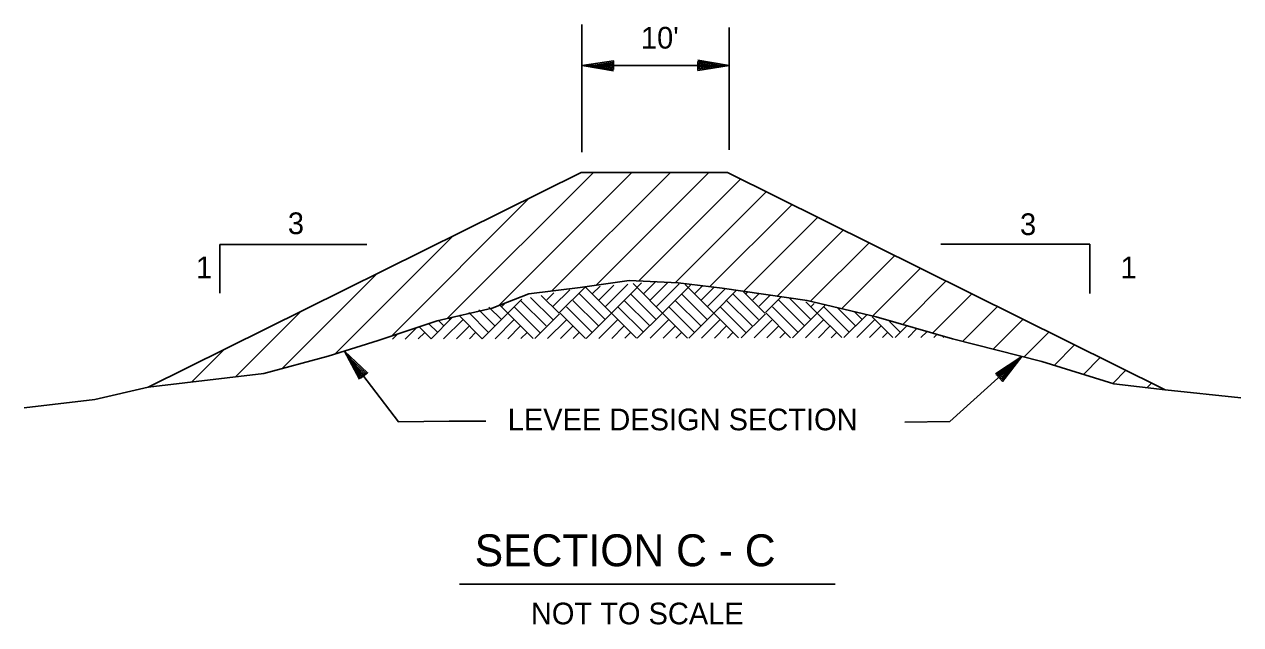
# Model space of a CAD drawing. Extents: x 2127959 to 2137375, y 2146193 to 2153470.
# Drawn here: x 2131652 to 2133498, y 2148312 to 2149223 of the extents above; entities that cross this region are included whole.
import ezdxf

# ---------------------------------------------------------------- set-up
doc = ezdxf.new("R2010")
doc.units = 0
for name, color, linetype in [('Level 1', 7, 'Continuous'), ('Level 3', 7, 'Continuous'), ('Level 5', 7, 'Continuous'), ('Level 50', 7, 'Continuous'), ('Level 63', 7, 'Continuous')]:
    doc.layers.add(name, color=color, linetype=linetype)

msp = doc.modelspace()

# ---------------------------------------------------------------- linework, layer by layer
at = {"layer": 'Level 1'}
for p, q in [((2132496.987, 2148998.226), (2131839.745, 2148672.512)), ((2132496.987, 2148998.226), (2131839.745, 2148672.512)), ((2132496.987, 2148998.226), (2131839.745, 2148672.512)), ((2132496.987, 2148998.226), (2132719.089, 2148998.226)), ((2132496.987, 2148998.226), (2132719.089, 2148998.226)), ((2132496.987, 2148998.226), (2132719.089, 2148998.226)), ((2132719.089, 2148998.226), (2133383.437, 2148668.257)), ((2132719.089, 2148998.226), (2133383.437, 2148668.257)), ((2132719.089, 2148998.226), (2133383.437, 2148668.257))]:
    msp.add_line(p, q, dxfattribs=at)
at = {"layer": 'Level 3'}
for p, q in [((2132497.781, 2149028.681), (2132497.781, 2149222.769)), ((2132721.264, 2149032.313), (2132721.264, 2149218.04)), ((2132497.781, 2149160.417), (2132609.509, 2149160.417)), ((2132721.264, 2149160.417), (2132609.509, 2149160.417)), ((2132171.512, 2148888.717), (2131948.22, 2148888.717)), ((2132171.512, 2148888.717), (2131948.22, 2148888.717)), ((2132171.512, 2148888.717), (2131948.22, 2148888.717)), ((2131948.22, 2148888.717), (2131948.22, 2148814.697)), ((2133042.777, 2148889.177), (2133268.647, 2148889.177)), ((2133042.777, 2148889.177), (2133268.647, 2148889.177)), ((2133042.777, 2148889.177), (2133268.647, 2148889.177)), ((2133268.647, 2148889.177), (2133268.647, 2148814.544)), ((2133268.647, 2148889.177), (2133268.647, 2148814.544)), ((2133268.647, 2148889.177), (2133268.647, 2148814.544))]:
    msp.add_line(p, q, dxfattribs=at)
for points in [[(2132137.319, 2148727.148), (2132219.454, 2148619.815), (2132296.18, 2148620.596), (2132352.068, 2148620.596)], [(2133165.513, 2148718.847), (2133056.395, 2148620.44), (2132987.946, 2148619.334)]]:
    msp.add_lwpolyline(points, dxfattribs=at)
at = {"layer": 'Level 5'}
for p, q in [((2132294.09, 2148776.813), (2132515.512, 2148998.226)), ((2132371.523, 2148795.886), (2132573.867, 2148998.226)), ((2132451.988, 2148818.019), (2132632.193, 2148998.226)), ((2132519.14, 2148826.799), (2132690.547, 2148998.226)), ((2132584.14, 2148833.467), (2132738.996, 2148988.325)), ((2132639.983, 2148830.979), (2132777.99, 2148968.962)), ((2132209.156, 2148750.201), (2132418.059, 2148959.107)), ((2132692.246, 2148824.887), (2132816.977, 2148949.598)), ((2132743.577, 2148817.864), (2132855.946, 2148930.234)), ((2132794.535, 2148810.497), (2132894.937, 2148910.874)), ((2132123.323, 2148722.735), (2132302.388, 2148901.789)), ((2132845.08, 2148802.683), (2132933.93, 2148891.531)), ((2132892.234, 2148791.485), (2132972.896, 2148872.17)), ((2132042.795, 2148700.549), (2132186.715, 2148844.471)), ((2132939.387, 2148780.304), (2133011.888, 2148852.805)), ((2132417.489, 2148813.748), (2132495.4, 2148823.365)), ((2132417.489, 2148813.748), (2132495.4, 2148823.365)), ((2132417.489, 2148813.748), (2132495.4, 2148823.365)), ((2132479.338, 2148820.108), (2132454.345, 2148795.093)), ((2132464.067, 2148785.363), (2132502.728, 2148824.028)), ((2132495.4, 2148823.365), (2132569.575, 2148834.103)), ((2132495.4, 2148823.365), (2132569.575, 2148834.103)), ((2132495.4, 2148823.365), (2132569.575, 2148834.103)), ((2132503.737, 2148823.501), (2132542.642, 2148784.596)), ((2132513.51, 2148813.792), (2132525.418, 2148825.719)), ((2132546.468, 2148827.283), (2132523.257, 2148804.046)), ((2132567.463, 2148828.825), (2132532.961, 2148794.321)), ((2132542.707, 2148784.596), (2132581.589, 2148823.501)), ((2132569.575, 2148834.103), (2132643.946, 2148830.8)), ((2132569.575, 2148834.103), (2132643.946, 2148830.8)), ((2132569.575, 2148834.103), (2132643.946, 2148830.8)), ((2132581.589, 2148823.501), (2132575.648, 2148829.439)), ((2132575.648, 2148829.439), (2132581.589, 2148823.501)), ((2132588.501, 2148830.384), (2132581.431, 2148823.322)), ((2132581.589, 2148823.501), (2132620.49, 2148784.596)), ((2132591.335, 2148813.748), (2132609.509, 2148831.947)), ((2132601.036, 2148804.046), (2132627.711, 2148830.69)), ((2132645.421, 2148828.911), (2132610.787, 2148794.302)), ((2132620.315, 2148784.751), (2132659.065, 2148823.475)), ((2132643.946, 2148830.8), (2132711.011, 2148822.593)), ((2132643.946, 2148830.8), (2132711.011, 2148822.593)), ((2132643.946, 2148830.8), (2132711.011, 2148822.593)), ((2132654.554, 2148828.008), (2132659.236, 2148823.322)), ((2132659.065, 2148823.475), (2132662.757, 2148827.198)), ((2132697.963, 2148784.596), (2132659.065, 2148823.475)), ((2132668.766, 2148813.775), (2132680.407, 2148825.434)), ((2132698.119, 2148823.65), (2132678.514, 2148804.026)), ((2132715.811, 2148821.894), (2132688.216, 2148794.321)), ((2132697.963, 2148784.596), (2132732.794, 2148819.428)), ((2132711.011, 2148822.593), (2132839.621, 2148803.961)), ((2132775.813, 2148784.596), (2132742.343, 2148818.041)), ((2132984.868, 2148767.441), (2133050.873, 2148833.444)), ((2132361.467, 2148791.966), (2132417.489, 2148813.748)), ((2132361.467, 2148791.966), (2132417.489, 2148813.748)), ((2132361.467, 2148791.966), (2132417.489, 2148813.748)), ((2132381.886, 2148800.48), (2132375.701, 2148794.302)), ((2132385.427, 2148784.572), (2132406.572, 2148805.716)), ((2132404.944, 2148804.026), (2132443.849, 2148765.126)), ((2132420.019, 2148808.383), (2132453.551, 2148774.841)), ((2132463.275, 2148784.572), (2132436.28, 2148811.596)), ((2132455.115, 2148815.318), (2132444.614, 2148804.815)), ((2132523.193, 2148765.149), (2132484.293, 2148804.046)), ((2132494.035, 2148813.792), (2132532.961, 2148774.868)), ((2132600.886, 2148765.316), (2132562.137, 2148804.046)), ((2132571.881, 2148813.792), (2132610.634, 2148775.058)), ((2132639.613, 2148804.026), (2132678.514, 2148765.143)), ((2132649.293, 2148813.775), (2132688.216, 2148774.857)), ((2132717.455, 2148804.026), (2132756.361, 2148765.143)), ((2132727.162, 2148813.775), (2132766.087, 2148774.857)), ((2132747.411, 2148814.567), (2132749.802, 2148816.987)), ((2132766.836, 2148814.5), (2132757.152, 2148804.815)), ((2132783.796, 2148812.056), (2132766.854, 2148795.116)), ((2132776.58, 2148785.389), (2132800.546, 2148809.352)), ((2132835.705, 2148765.16), (2132796.827, 2148804.07)), ((2132813.639, 2148806.732), (2132845.494, 2148774.881)), ((2132837.839, 2148801.91), (2132855.155, 2148784.616)), ((2132839.621, 2148803.961), (2132944.753, 2148779.033)), ((2132839.621, 2148803.961), (2132944.753, 2148779.033)), ((2132839.621, 2148803.961), (2132944.753, 2148779.033)), ((2132850.534, 2148799.38), (2132845.494, 2148794.344)), ((2133030.15, 2148754.363), (2133089.841, 2148814.082)), ((2131971.897, 2148687.996), (2132071.068, 2148787.149)), ((2132278.028, 2148773.192), (2132361.467, 2148791.966)), ((2132278.028, 2148773.192), (2132361.467, 2148791.966)), ((2132278.028, 2148773.192), (2132361.467, 2148791.966)), ((2132346.68, 2148745.847), (2132311.034, 2148781.515)), ((2132356.231, 2148755.375), (2132326.088, 2148785.542)), ((2132341.448, 2148789.656), (2132365.979, 2148765.126)), ((2132385.427, 2148784.572), (2132346.594, 2148745.746)), ((2132356.758, 2148793.775), (2132375.701, 2148774.841)), ((2132385.427, 2148784.572), (2132372.115, 2148797.885)), ((2132424.091, 2148745.985), (2132385.496, 2148784.572)), ((2132434.098, 2148755.375), (2132395.152, 2148794.302)), ((2132464.067, 2148783.805), (2132426.24, 2148745.992)), ((2132464.838, 2148784.596), (2132503.212, 2148746.229)), ((2132513.51, 2148755.407), (2132474.568, 2148794.321)), ((2132542.707, 2148784.596), (2132504.335, 2148746.23)), ((2132542.707, 2148784.596), (2132580.819, 2148746.466)), ((2132591.161, 2148755.596), (2132552.433, 2148794.321)), ((2132582.027, 2148746.473), (2132620.315, 2148784.751)), ((2132658.356, 2148746.711), (2132620.315, 2148784.751)), ((2132668.766, 2148755.39), (2132629.842, 2148794.321)), ((2132697.963, 2148784.596), (2132660.097, 2148746.713)), ((2132735.657, 2148746.942), (2132698.03, 2148784.596)), ((2132746.614, 2148755.39), (2132707.687, 2148794.321)), ((2132776.58, 2148783.826), (2132739.727, 2148746.952)), ((2132777.374, 2148784.616), (2132814.779, 2148747.187)), ((2132826.022, 2148755.414), (2132787.102, 2148794.344)), ((2132855.22, 2148784.616), (2132817.82, 2148747.199)), ((2132855.22, 2148784.616), (2132866.777, 2148796.148)), ((2132855.22, 2148784.616), (2132892.409, 2148747.43)), ((2132903.698, 2148755.614), (2132864.948, 2148794.344)), ((2132913.402, 2148765.322), (2132886.512, 2148792.231)), ((2132895.514, 2148747.436), (2132929.682, 2148781.602)), ((2132911.662, 2148786.554), (2132923.146, 2148775.076)), ((2133075.809, 2148741.689), (2133128.834, 2148794.719)), ((2132188.674, 2148743.367), (2132278.028, 2148773.192)), ((2132188.674, 2148743.367), (2132278.028, 2148773.192)), ((2132188.674, 2148743.367), (2132278.028, 2148773.192)), ((2132229.865, 2148745.385), (2132247.116, 2148762.64)), ((2132250.942, 2148763.82), (2132269.074, 2148745.692)), ((2132278.648, 2148755.582), (2132265.796, 2148768.407)), ((2132268.9, 2148745.847), (2132302.212, 2148779.152)), ((2132288.35, 2148765.306), (2132280.667, 2148772.999)), ((2132288.02, 2148745.566), (2132317.526, 2148775.076)), ((2132295.743, 2148777.419), (2132298.098, 2148775.05)), ((2132327.255, 2148765.29), (2132307.559, 2148745.623)), ((2132366.131, 2148745.807), (2132395.152, 2148774.841)), ((2132385.602, 2148745.861), (2132404.881, 2148765.126)), ((2132445.759, 2148746.056), (2132473.794, 2148774.077)), ((2132465.259, 2148746.112), (2132483.52, 2148764.361)), ((2132523.852, 2148746.288), (2132552.433, 2148774.868)), ((2132543.347, 2148746.351), (2132562.137, 2148765.149)), ((2132601.505, 2148746.532), (2132630.06, 2148775.089)), ((2132639.761, 2148765.312), (2132621.063, 2148746.592)), ((2132679.615, 2148746.773), (2132707.687, 2148774.857)), ((2132699.108, 2148746.835), (2132717.413, 2148765.143)), ((2132759.265, 2148747.02), (2132786.331, 2148774.09)), ((2132778.737, 2148747.075), (2132796.034, 2148764.373)), ((2132837.354, 2148747.258), (2132864.948, 2148774.881)), ((2132856.826, 2148747.32), (2132874.673, 2148765.16)), ((2132914.985, 2148747.497), (2132942.576, 2148775.099)), ((2132952.298, 2148765.319), (2132934.547, 2148747.556)), ((2132969.947, 2148747.669), (2132938.397, 2148779.216)), ((2132944.753, 2148779.033), (2133060.534, 2148745.58)), ((2132944.753, 2148779.033), (2133060.534, 2148745.58)), ((2132944.753, 2148779.033), (2133060.534, 2148745.58)), ((2132981.299, 2148755.407), (2132964.695, 2148772.004)), ((2132990.74, 2148764.854), (2132973.558, 2148747.68)), ((2133122.323, 2148729.845), (2133167.825, 2148775.351)), ((2132210.367, 2148745.325), (2132219.016, 2148753.963)), ((2132259.37, 2148755.39), (2132249.404, 2148745.446)), ((2132336.999, 2148755.614), (2132327.073, 2148745.686)), ((2132414.624, 2148755.375), (2132405.162, 2148745.927)), ((2132493.271, 2148754.613), (2132484.815, 2148746.171)), ((2132571.881, 2148755.407), (2132562.907, 2148746.41)), ((2132649.512, 2148755.622), (2132640.535, 2148746.651)), ((2132727.162, 2148755.39), (2132718.668, 2148746.896)), ((2132805.781, 2148754.627), (2132798.301, 2148747.138)), ((2132884.422, 2148755.414), (2132876.389, 2148747.382)), ((2132962.045, 2148755.632), (2132954.019, 2148747.619)), ((2132993.096, 2148747.736), (2133006.008, 2148760.657)), ((2133012.595, 2148747.803), (2133021.258, 2148756.48)), ((2133036.552, 2148752.278), (2133032.151, 2148747.86)), ((2133047.224, 2148747.904), (2133045.245, 2148749.897)), ((2133060.534, 2148745.58), (2133196.254, 2148711.019)), ((2133060.534, 2148745.58), (2133196.254, 2148711.019)), ((2133060.534, 2148745.58), (2133196.254, 2148711.019)), ((2133168.818, 2148718.007), (2133206.815, 2148755.987)), ((2131905.825, 2148680.256), (2131955.395, 2148729.835)), ((2132112.741, 2148719.384), (2132188.674, 2148743.367)), ((2132112.741, 2148719.384), (2132188.674, 2148743.367)), ((2132112.741, 2148719.384), (2132188.674, 2148743.367)), ((2133214.54, 2148705.368), (2133245.78, 2148736.626)), ((2132014.892, 2148693.034), (2132112.741, 2148719.384)), ((2132014.892, 2148693.034), (2132112.741, 2148719.384)), ((2132014.892, 2148693.034), (2132112.741, 2148719.384)), ((2133196.254, 2148711.019), (2133305.519, 2148677.253)), ((2133196.254, 2148711.019), (2133305.519, 2148677.253)), ((2133196.254, 2148711.019), (2133305.519, 2148677.253)), ((2133259.094, 2148691.597), (2133284.771, 2148717.264)), ((2131839.745, 2148672.512), (2132014.892, 2148693.034)), ((2131839.745, 2148672.512), (2132014.892, 2148693.034)), ((2131839.745, 2148672.512), (2132014.892, 2148693.034)), ((2133303.671, 2148677.821), (2133323.763, 2148697.905)), ((2131758.664, 2148653.735), (2131839.745, 2148672.512)), ((2131758.664, 2148653.735), (2131839.745, 2148672.512)), ((2131758.664, 2148653.735), (2131839.745, 2148672.512)), ((2133305.519, 2148677.253), (2133383.437, 2148668.257)), ((2133305.519, 2148677.253), (2133383.437, 2148668.257)), ((2133305.519, 2148677.253), (2133383.437, 2148668.257)), ((2133355.665, 2148671.463), (2133362.733, 2148678.54)), ((2131651.552, 2148641.115), (2131758.664, 2148653.735)), ((2131651.552, 2148641.115), (2131758.664, 2148653.735)), ((2131651.552, 2148641.115), (2131758.664, 2148653.735)), ((2133383.437, 2148668.257), (2133497.853, 2148656.264)), ((2133383.437, 2148668.257), (2133497.853, 2148656.264)), ((2133383.437, 2148668.257), (2133497.853, 2148656.264))]:
    msp.add_line(p, q, dxfattribs=at)
at = {"layer": 'Level 50'}
for p, q in [((2132498.491, 2149160.146), (2132498.491, 2149160.146)), ((2132511.614, 2149160.042), (2132511.614, 2149160.042)), ((2132708.125, 2149160.475), (2132708.125, 2149160.475)), ((2132721.25, 2149160.37), (2132721.25, 2149160.37)), ((2132137.524, 2148726.851), (2132137.524, 2148726.851)), ((2132145.515, 2148716.455), (2132145.515, 2148716.455)), ((2133155.879, 2148709.905), (2133155.879, 2148709.905)), ((2133165.544, 2148718.786), (2133165.544, 2148718.786))]:
    msp.add_line(p, q, dxfattribs=at)
for points in [[(2132674.109, 2149168.535), (2132721.25, 2149160.37), (2132674.013, 2149152.882), (2132674.106, 2149166.254), (2132708.125, 2149160.475), (2132676.059, 2149155.396), (2132676.101, 2149163.987), (2132695.51, 2149160.565), (2132678.088, 2149157.903), (2132678.11, 2149161.429), (2132682.384, 2149160.652)], [(2132545.63, 2149151.986), (2132498.491, 2149160.146), (2132545.725, 2149167.632), (2132545.632, 2149154.264), (2132511.614, 2149160.042), (2132543.679, 2149165.12), (2132543.633, 2149156.536), (2132524.228, 2149159.95), (2132541.65, 2149162.61), (2132541.631, 2149159.085), (2132537.352, 2149159.865)], [(2132160.11, 2148684.689), (2132137.524, 2148726.851), (2132172.51, 2148694.242), (2132161.914, 2148686.085), (2132145.515, 2148716.455), (2132169.261, 2148694.309), (2132162.471, 2148689.055), (2132153.213, 2148706.452), (2132166.037, 2148694.368), (2132163.24, 2148692.207), (2132161.23, 2148696.06)], [(2133125.508, 2148692.609), (2133165.544, 2148718.786), (2133136.108, 2148681.108), (2133127.054, 2148690.963), (2133155.879, 2148709.905), (2133135.895, 2148684.319), (2133130.071, 2148690.675), (2133146.584, 2148701.378), (2133135.654, 2148687.552), (2133133.26, 2148690.153), (2133136.935, 2148692.496)]]:
    msp.add_lwpolyline(points, dxfattribs=at)
at = {"layer": 'Level 63'}
msp.add_line((2132312.054, 2148373.481), (2132882.281, 2148373.481), dxfattribs=at)

# ---------------------------------------------------------------- texts
at = {"layer": 'Level 1'}
for s, p in [("10'", (2132587.531, 2149186.004)), ('3', (2132051.594, 2148904.492)), ('3', (2133162.918, 2148903.06)), ('1', (2131912.136, 2148837.581)), ('1', (2133315.577, 2148837.43)), ('LEVEE DESIGN SECTION', (2132385.341, 2148606.872)), ('NOT TO SCALE', (2132420.478, 2148312.487))]:
    msp.add_text(s, height=32.931, dxfattribs=at).set_placement(p)
at = {"layer": 'Level 63'}
msp.add_text('SECTION C - C', height=48.4, dxfattribs=at).set_placement((2132335.209, 2148400.621))

doc.saveas('drawing.dxf')
